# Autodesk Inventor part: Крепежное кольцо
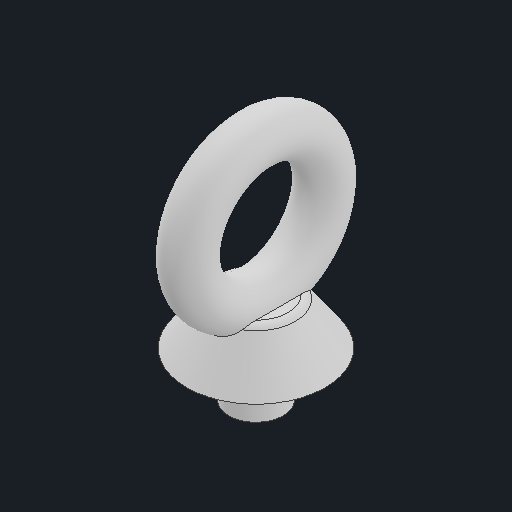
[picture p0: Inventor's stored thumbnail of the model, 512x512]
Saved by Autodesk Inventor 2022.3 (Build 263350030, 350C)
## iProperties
Created: 2020-09
Part Number: Крепежное кольцо
Material: Типовые
Document SubType Name: Modeling
Designer: Карташов
Density: 1 g/cm^3
Appearance: По умолчанию
Title: D:\мои документы\Ирина\_WorldSkills\2020_09 ФНЧ\Module A\GIVEN\Крепежное кольцо.stp
Author: Дом
Sending System: Autodesk Inventor 2021
Preprocessor: ST-DEVELOPER v18.1
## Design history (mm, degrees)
feature "Твердое тело2"
node "Твердое тело1"
